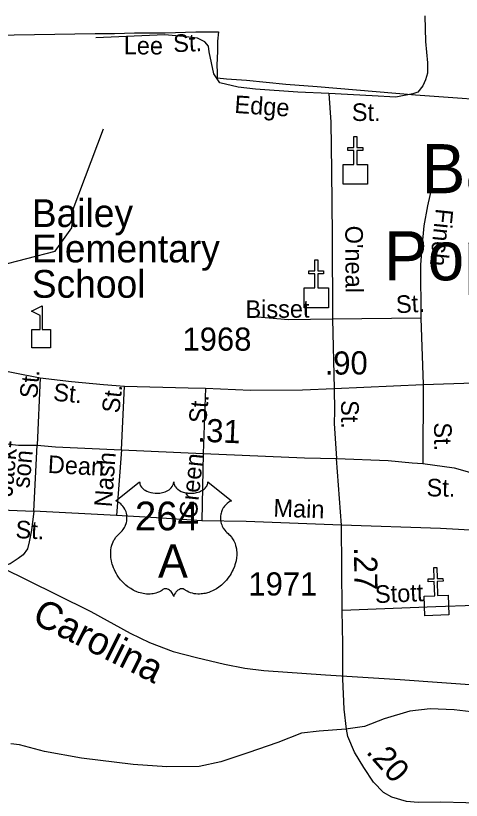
# Model space of a CAD drawing. Extents: x 2220236 to 2384410, y 720751 to 894131.
# Drawn here: x 2262372 to 2264776, y 738060 to 742297 of the extents above; entities that cross this region are included whole.
import ezdxf

# ---------------------------------------------------------------- set-up
doc = ezdxf.new("R2010")
doc.units = 0
for name, color, linetype in [('Exist Boundary Political City Limit New', 7, 'Continuous'), ('Exist Civil Demographics City Label', 7, 'Continuous'), ('Exist Cultural Church CELL', 7, 'Continuous'), ('Exist Cultural Educational Facility Elementary CELL', 7, 'Continuous'), ('Exist Cultural Educational Facility Elementary Label', 7, 'Continuous'), ('Exist Hydrographic Creek Single Shore', 7, 'Continuous'), ('Exist Railroad Mainline', 7, 'Continuous'), ('Exist Railroad Mainline Label', 7, 'Continuous'), ('Exist Road Non-System Type 51', 7, 'Continuous'), ('Exist Road Non-System Type 51 Label', 7, 'Continuous'), ('Exist Road Primary US Attributed', 7, 'Continuous'), ('Exist Road Primary US Label', 7, 'Continuous'), ('Exist Road Primary US Mileage Hundredths English Label', 7, 'Continuous'), ('Exist Road Primary US Shield CELL', 7, 'Continuous'), ('Exist Road Primary US Shield Number Label', 7, 'Continuous'), ('Exist Road Secondary Mileage Hundredths English Label', 7, 'Continuous'), ('Exist Road Secondary Type 51 Attributed', 7, 'Continuous'), ('Exist Road Secondary Type 51 Label', 7, 'Continuous'), ('Exist Road Secondary Type 51 Number Label', 7, 'Continuous'), ('Map Preparation Boundary City Limit Buffer Line', 7, 'Continuous')]:
    doc.layers.add(name, color=color, linetype=linetype)

msp = doc.modelspace()

# ---------------------------------------------------------------- linework, layer by layer
at = {"layer": 'Exist Boundary Political City Limit New'}
for points in [[(2261817.5, 742185.4), (2262801, 742201.3), (2262904.2, 742201.3), (2263013, 742203.9), (2263177.5, 742205.2), (2263344, 742209.2), (2263383, 742210.6), (2263466.8, 742210.6), (2263461.2, 742158.8), (2263460, 742105.8), (2263457.5, 742030.1), (2263458.8, 741992.9), (2263458.8, 741961.1), (2263508.8, 741955.8), (2263617.2, 741949.2), (2263829.5, 741927.9), (2263999.2, 741914.7), (2264529.8, 741869.6)], [(2264529.8, 741869.6), (2265081.2, 741829.8)], [(2264830.2, 738538.5), (2264738.2, 738548.2), (2264608.2, 738553.5), (2264498.2, 738540.9), (2264360.5, 738500.4), (2264253.8, 738458.8), (2264152.8, 738443.3), (2264008.8, 738432.6), (2263914.8, 738422.2), (2263787, 738371.4), (2263625.2, 738316.8), (2263479.5, 738268), (2263361.8, 738243.4), (2263187.8, 738240.6), (2263005.8, 738253.8), (2262727.5, 738288.2), (2262527.2, 738323.3), (2262393.2, 738358.8), (2262345.2, 738364.5)]]:
    msp.add_lwpolyline(points, dxfattribs=at)
at = {"layer": 'Exist Cultural Church CELL'}
for points in [[(2264139.3, 741493.1), (2264196.2, 741493.2), (2264196.2, 741569.4), (2264164.2, 741569.4), (2264164.2, 741585.3), (2264196.2, 741585.3), (2264196.2, 741645.5), (2264212.2, 741645.5), (2264212.2, 741585.3), (2264244.2, 741585.3), (2264244.2, 741569.4), (2264212.2, 741569.4), (2264212.2, 741493.2), (2264269.9, 741493.1), (2264269.9, 741386.7), (2264139.3, 741386.7)], [(2263928.5, 740826.6), (2263985.4, 740826.8), (2263985.4, 740902.9), (2263953.4, 740902.9), (2263953.4, 740918.9), (2263985.4, 740918.9), (2263985.4, 740979), (2264001.4, 740979), (2264001.4, 740918.9), (2264033.4, 740918.9), (2264033.4, 740902.9), (2264001.4, 740902.9), (2264001.4, 740826.8), (2264059.1, 740826.6), (2264059.1, 740720.2), (2263928.5, 740720.2)], [(2264575.6, 739162.9), (2264632.5, 739164.9), (2264629.9, 739241), (2264598, 739239.9), (2264597.4, 739255.9), (2264629.4, 739256.9), (2264627.4, 739317.1), (2264643.4, 739317.6), (2264645.4, 739257.5), (2264677.4, 739258.5), (2264677.9, 739242.6), (2264646, 739241.5), (2264648.5, 739165.4), (2264706.1, 739167.2), (2264709.6, 739060.8), (2264579.1, 739056.5)]]:
    msp.add_lwpolyline(points, close=True, dxfattribs=at)
at = {"layer": 'Exist Cultural Educational Facility Elementary CELL'}
msp.add_lwpolyline([(2262458.7, 740504.2), (2262458.7, 740602.1), (2262504.7, 740602.1), (2262504.7, 740677.2), (2262457.7, 740701.5), (2262514.3, 740730.7), (2262514.3, 740602.1), (2262560.4, 740602.1), (2262560.4, 740504.2)], close=True, dxfattribs=at)
at = {"layer": 'Exist Hydrographic Creek Single Shore'}
msp.add_lwpolyline([(2262277.2, 740946.5), (2262584.4, 741025.4), (2262675.4, 741151.5), (2262682.4, 741253), (2262845.4, 741685.9)], dxfattribs=at)
at = {"layer": 'Exist Railroad Mainline'}
msp.add_lwpolyline([(2262292.6, 739319), (2262591.9, 739171.9), (2262776.5, 739079.7), (2262989.6, 738961.8), (2263094, 738912.9), (2263222.3, 738864), (2263346.6, 738831.3), (2263498.8, 738794.8), (2263609, 738773.7), (2263711.1, 738760.6), (2264043.1, 738737.8), (2264447.2, 738711.7), (2264921.4, 738678.1), (2265321.4, 738655.9), (2265719.3, 738639.7), (2266099.3, 738615.3), (2266235.2, 738612.5), (2266365.4, 738597.6), (2266485.6, 738577), (2266585.7, 738545.9), (2266703.9, 738516.9), (2266814.4, 738474)], dxfattribs=at)
at = {"layer": 'Exist Road Non-System Type 51'}
for p, q in [((2264557, 740663.6), (2264081, 740658.7)), ((2264081, 740658.7), (2264090.7, 740284.5)), ((2264557, 740663.6), (2264570.6, 740305.4)), ((2262504, 740341.3), (2262487.9, 739977.3)), ((2262942.2, 739952.8), (2262959.8, 740296)), ((2263396.6, 740285.8), (2263383.4, 739933.5)), ((2264570.6, 740305.4), (2264569, 739878.1)), ((2262942.2, 739952.8), (2262915.6, 739598.7)), ((2263383.4, 739933.5), (2263376.1, 739569.5)), ((2262915.6, 739598.7), (2262470.4, 739622.1))]:
    msp.add_line(p, q, dxfattribs=at)
for points in [[(2264579.4, 742297.1), (2264582.7, 742157.1), (2264593.7, 742043.3), (2264594.4, 741987.3), (2264582.7, 741951.2), (2264569, 741919.1), (2264541.3, 741884.9), (2264515.5, 741874.6), (2264423.6, 741857.9), (2264295.6, 741864.5), (2264061.8, 741876.3)], [(2264061.8, 741876.3), (2263893.7, 741884.8), (2263665.7, 741900.7), (2263571.6, 741911.8), (2263473.5, 741934.8), (2263440.9, 741982.5), (2263415.9, 742102.2), (2263411.6, 742132.2), (2263391.5, 742156.1), (2263353.3, 742175.6), (2263275.1, 742184.8), (2263177.1, 742193.8), (2262803.5, 742178.3)], [(2264061.8, 741876.3), (2264071.4, 741722.1), (2264076.2, 741458.7), (2264080.2, 741110.1), (2264081, 740658.7)], [(2264619.6, 741381.6), (2264593.9, 741270.7), (2264574.6, 741161.5), (2264563.4, 741045.8), (2264555.4, 740951.1), (2264557, 740663.6)], [(2264081, 740658.7), (2263843.5, 740655.5), (2263634.8, 740673.2)], [(2264090.7, 740284.5), (2264092.3, 740162.4), (2264090.7, 740094.9), (2264102.7, 739905.4)], [(2262470.4, 739622.1), (2262456.7, 739518.6), (2262445.2, 739456.4), (2262435.6, 739418.5), (2262411.9, 739386.1), (2262386.1, 739365.9), (2262342.4, 739337.6), (2262218.9, 739294.4), (2262131, 739277.6), (2262057, 739276.9), (2261967, 739283.9), (2261789, 739292.4), (2261482.9, 739319.5), (2261057, 739347.5)], [(2263376.1, 739569.5), (2263132.2, 739585.6), (2262915.6, 739598.7)], [(2264129.5, 739546.1), (2263615.6, 739565.3), (2263376.1, 739569.5)], [(2265471.4, 739484.9), (2265293.5, 739497.2), (2265113.5, 739503.5), (2264663.5, 739527.4), (2264129.5, 739546.1)], [(2265997.1, 739150), (2265901.8, 739147.8), (2265404.8, 739134.4), (2265059, 739119.1), (2264639.4, 739105.2), (2264133.8, 739084.6)]]:
    msp.add_lwpolyline(points, dxfattribs=at)
at = {"layer": 'Exist Road Primary US Attributed'}
for points in [[(2261239.8, 740172.1), (2261385.9, 740142.9), (2261438.2, 740132.2), (2261767.2, 740058.1), (2261937.2, 740022.7), (2262035.1, 740003.7), (2262116.3, 739993), (2262185.5, 739990.5), (2262249.8, 739989), (2262321.4, 739984.7), (2262386.3, 739977.7), (2262487.9, 739977.3)], [(2262487.9, 739977.3), (2262586.3, 739969.6), (2262942.2, 739952.8), (2263383.4, 739933.5), (2263929.3, 739910.2), (2264102.7, 739905.4)], [(2264102.7, 739905.4), (2264382, 739894.2), (2264510.4, 739882.9), (2264569, 739878.1), (2264738.4, 739855.6), (2264820.6, 739832.6), (2264898.9, 739804.2), (2264977.6, 739770.5), (2265061, 739720.7), (2265178.2, 739661.3), (2265314.4, 739591.3), (2265471.4, 739484.9), (2265558.1, 739421.8), (2265688.8, 739340.9), (2265827.4, 739258.3), (2265906.6, 739208.1), (2265997.1, 739150), (2266082.8, 739094.9), (2266256.1, 738983.4), (2266450.4, 738858.1), (2266604.5, 738761.8), (2266771.4, 738650.9), (2267068.3, 738464.4), (2267306.7, 738310.4)]]:
    msp.add_lwpolyline(points, dxfattribs=at)
at = {"layer": 'Exist Road Primary US Shield CELL'}
msp.add_lwpolyline([(2263040.5, 739779.4), (2263040.8, 739774.1), (2263042.1, 739767.8), (2263043.1, 739764.5), (2263046, 739758.3), (2263050.9, 739750.9), (2263057.7, 739743.7), (2263065.4, 739737.4), (2263070.5, 739734.1), (2263079.3, 739729.4), (2263089.3, 739725.2), (2263100.3, 739722), (2263111.7, 739719.7), (2263124, 739718.3), (2263136.3, 739718.1), (2263149.5, 739719.1), (2263164.1, 739721.9), (2263170.8, 739723.7), (2263178.3, 739726.2), (2263185.3, 739729.1), (2263193, 739733.2), (2263199.2, 739737.2), (2263204, 739740.7), (2263210.8, 739747.2), (2263216.2, 739754), (2263218.5, 739757.8), (2263220.5, 739761.4), (2263223.2, 739769.2), (2263224, 739772.6), (2263224.5, 739779.7), (2263224.9, 739773.7), (2263225.6, 739770), (2263226.5, 739766.4), (2263228.1, 739762.5), (2263230.8, 739757), (2263233.8, 739752.4), (2263239.6, 739745.7), (2263243.1, 739742.3), (2263246.4, 739739.7), (2263255.1, 739733.7), (2263265.3, 739728.5), (2263270.4, 739726.3), (2263275.5, 739724.5), (2263282.1, 739722.5), (2263288.8, 739720.9), (2263295.5, 739719.8), (2263302.3, 739718.8), (2263309.3, 739718.3), (2263315, 739718.1), (2263322, 739718.2), (2263328.5, 739718.6), (2263335.1, 739719.3), (2263342.4, 739720.5), (2263348.2, 739721.8), (2263356, 739723.9), (2263362.9, 739726.4), (2263369.1, 739729), (2263377.1, 739733.2), (2263383.5, 739737.3), (2263388.2, 739741.1), (2263393.9, 739746.2), (2263399.2, 739752.4), (2263402.3, 739756.9), (2263404.5, 739761.5), (2263406.5, 739766.4), (2263407.8, 739771.5), (2263408.4, 739776), (2263408.5, 739779.8), (2263537.1, 739677.4), (2263534.1, 739676.2), (2263527.1, 739672.8), (2263521.6, 739669.5), (2263512.7, 739663.3), (2263508.9, 739659.9), (2263505.1, 739656.3), (2263501.6, 739652.5), (2263498.5, 739649), (2263494.8, 739643.8), (2263491.5, 739638.6), (2263488.2, 739632.9), (2263485.8, 739628), (2263481.9, 739617.6), (2263480, 739611.1), (2263478.8, 739605.6), (2263477.2, 739594.1), (2263476.9, 739588.6), (2263476.9, 739583.2), (2263477.2, 739577.5), (2263477.7, 739572.1), (2263478.7, 739566.4), (2263479.6, 739561.3), (2263481.2, 739555.2), (2263483.5, 739548), (2263486.3, 739541.1), (2263492.2, 739530), (2263499.7, 739518.6), (2263505.1, 739512.2), (2263510.4, 739506.7), (2263518.4, 739500), (2263522.7, 739496.2), (2263527.6, 739491.3), (2263535.6, 739481.9), (2263538.9, 739477.5), (2263542.2, 739472.6), (2263545.3, 739467.5), (2263548.3, 739462), (2263550.7, 739457.2), (2263555.2, 739446.2), (2263558.5, 739435.5), (2263560.1, 739429.9), (2263562.5, 739417.3), (2263563.4, 739411), (2263564.4, 739398.7), (2263564.4, 739383.8), (2263563.2, 739369.7), (2263560.6, 739353.2), (2263558.4, 739343.3), (2263555, 739331.9), (2263551.7, 739321.9), (2263545.9, 739307.2), (2263540.7, 739296.6), (2263533.9, 739284.1), (2263529.3, 739276.6), (2263523.9, 739268.6), (2263517.1, 739259.3), (2263509.2, 739249.4), (2263499.7, 739239), (2263492, 739231.3), (2263482, 739222.4), (2263475.9, 739217.3), (2263467.3, 739210.8), (2263455.4, 739202.9), (2263443.7, 739196.1), (2263433.8, 739191.1), (2263425, 739187.3), (2263413.6, 739182.9), (2263394.6, 739177.7), (2263387.7, 739176.2), (2263379.5, 739175), (2263371.8, 739174.3), (2263364.4, 739173.8), (2263354.4, 739173.8), (2263344.4, 739174.6), (2263335, 739175.9), (2263325.2, 739178), (2263314.9, 739181), (2263305.6, 739184.7), (2263296.2, 739189.3), (2263280.3, 739199.3), (2263275.7, 739201.8), (2263273.1, 739202.5), (2263267, 739202.8), (2263261.2, 739201.5), (2263255.3, 739199.2), (2263251.7, 739197.3), (2263247, 739194.2), (2263243.3, 739191.3), (2263238.9, 739187.1), (2263235.9, 739183.6), (2263233.6, 739180.9), (2263229.1, 739173.8), (2263227.5, 739170.5), (2263225.8, 739166.1), (2263224.4, 739159.8), (2263222.3, 739167.8), (2263220, 739173.1), (2263217.2, 739177.7), (2263214.4, 739181.7), (2263209.9, 739186.9), (2263205.9, 739190.8), (2263201, 739194.7), (2263195.9, 739197.8), (2263191.7, 739199.9), (2263187.9, 739201.4), (2263183.3, 739202.5), (2263179.5, 739202.8), (2263176.4, 739202.8), (2263172.1, 739201.8), (2263166.3, 739197.6), (2263160.8, 739193.8), (2263154.8, 739190.1), (2263147.6, 739186.3), (2263142.4, 739183.8), (2263136.2, 739181.4), (2263128.9, 739179), (2263121, 739176.9), (2263112.8, 739175.3), (2263105.7, 739174.2), (2263098, 739173.5), (2263091.1, 739173.3), (2263083.9, 739173.4), (2263077.2, 739173.9), (2263069.3, 739174.6), (2263059.6, 739176), (2263051.6, 739177.8), (2263043.1, 739180.1), (2263034.3, 739182.8), (2263025, 739186.4), (2263013.3, 739191.5), (2263005.2, 739195.7), (2262992.3, 739203.1), (2262977.3, 739213.5), (2262965.9, 739222.7), (2262957.6, 739230.2), (2262945.4, 739242.7), (2262938.2, 739250.8), (2262926.9, 739265.4), (2262919.7, 739275.9), (2262915, 739283.7), (2262908.2, 739296.1), (2262904.4, 739304), (2262899.6, 739315.4), (2262895.8, 739325.8), (2262892.6, 739335.7), (2262890.9, 739342), (2262888.4, 739353), (2262886.9, 739360.8), (2262885.5, 739371.5), (2262884.7, 739382.8), (2262884.6, 739393.3), (2262884.8, 739401.9), (2262885.8, 739412), (2262887.5, 739422.7), (2262889.6, 739431.9), (2262891.4, 739438.5), (2262894.2, 739446.6), (2262897.8, 739455.5), (2262902, 739464), (2262906.1, 739471.1), (2262911.2, 739478.7), (2262916.2, 739485.1), (2262922.8, 739492.3), (2262929.6, 739498.8), (2262935.9, 739503.9), (2262943.3, 739511.2), (2262947.2, 739515.6), (2262951.8, 739521.7), (2262955.6, 739527.4), (2262958.5, 739532.5), (2262962.4, 739540.1), (2262964.8, 739545.7), (2262967.8, 739554.3), (2262969.2, 739560.4), (2262970.8, 739568.3), (2262971.7, 739575.6), (2262972.1, 739584.8), (2262971.9, 739592.4), (2262970.9, 739601.3), (2262969.2, 739609.8), (2262967.2, 739617.3), (2262964, 739625.8), (2262961.1, 739632), (2262956.2, 739640.4), (2262950.7, 739648.3), (2262945, 739654.7), (2262939.3, 739660.4), (2262933.9, 739664.6), (2262928.7, 739668.3), (2262922.1, 739672.3), (2262915.8, 739675.4), (2262911.9, 739677)], close=True, dxfattribs=at)
at = {"layer": 'Exist Road Secondary Type 51 Attributed'}
for points in [[(2261387.4, 740581.4), (2261642.8, 740527), (2261872.2, 740470), (2262072.3, 740427.6), (2262358.6, 740370.6), (2262504, 740341.3), (2262672.9, 740322.1), (2262844.9, 740305.7), (2262959.8, 740296), (2263301.6, 740287.2), (2263396.6, 740285.8), (2263639.1, 740275.5), (2263918.9, 740276.5), (2264090.7, 740284.5), (2264570.6, 740305.4), (2265395.7, 740332.7), (2265870.1, 740351.9), (2266084.5, 740362.5), (2266279.4, 740366.4), (2266759.4, 740372.8), (2267114.1, 740384.1), (2267238.5, 740385.7), (2267291.5, 740385.7)], [(2261072.2, 739690.5), (2261352.5, 739676.2), (2261654.1, 739660.5), (2262021.9, 739639.7), (2262470.4, 739622.1), (2262487.9, 739977.3)], [(2264136.5, 738731.8), (2264137.6, 738904.2), (2264133.8, 739084.6), (2264129.5, 739546.1), (2264102.7, 739905.4)], [(2265133.3, 738040.6), (2264800.2, 738047), (2264665.3, 738050.2), (2264543.3, 738048.6), (2264480.7, 738053.4), (2264400.5, 738077.5), (2264357.1, 738101.6), (2264302.6, 738157.8), (2264249.6, 738236.5), (2264199.8, 738320), (2264164.5, 738405.2), (2264157.2, 738443.7), (2264143.6, 738551.3), (2264136.4, 738715.2), (2264136.5, 738731.8)]]:
    msp.add_lwpolyline(points, dxfattribs=at)
at = {"layer": 'Map Preparation Boundary City Limit Buffer Line'}
for points in [[(2261817.5, 742185.4), (2262801, 742201.3), (2262904.2, 742201.3), (2263013, 742203.9), (2263177.5, 742205.2), (2263344, 742209.2), (2263383, 742210.6), (2263466.8, 742210.6), (2263461.2, 742158.8), (2263460, 742105.8), (2263457.5, 742030.1), (2263458.8, 741992.9), (2263458.8, 741961.1), (2263508.8, 741955.8), (2263617.2, 741949.2), (2263829.5, 741927.9), (2263999.2, 741914.7), (2264529.8, 741869.6)], [(2264529.8, 741869.6), (2265081.2, 741829.8)], [(2264830.2, 738538.5), (2264738.2, 738548.2), (2264608.2, 738553.5), (2264498.2, 738540.9), (2264360.5, 738500.4), (2264253.8, 738458.8), (2264152.8, 738443.3), (2264008.8, 738432.6), (2263914.8, 738422.2), (2263787, 738371.4), (2263625.2, 738316.8), (2263479.5, 738268), (2263361.8, 738243.4), (2263187.8, 738240.6), (2263005.8, 738253.8), (2262727.5, 738288.2), (2262527.2, 738323.3), (2262393.2, 738358.8), (2262345.2, 738364.5)]]:
    msp.add_lwpolyline(points, dxfattribs=at)

# ---------------------------------------------------------------- texts
at = {"layer": 'Exist Civil Demographics City Label'}
for s, p in [('Bailey', (2264561.8, 741338.5)), ('Pop. 681', (2264358.4, 740868.1))]:
    msp.add_text(s, height=265, dxfattribs=at).set_placement(p)
at = {"layer": 'Exist Cultural Educational Facility Elementary Label'}
for s, p in [('Bailey', (2262458.8, 741155.9)), ('Elementary', (2262458.8, 740964.8)), ('School', (2262458.8, 740773.8))]:
    msp.add_text(s, height=150, dxfattribs=at).set_placement(p)
at = {"layer": 'Exist Railroad Mainline Label'}
msp.add_text('Carolina', height=150, rotation=333.4602, dxfattribs=at).set_placement((2262452.7, 739022.3))
at = {"layer": 'Exist Road Non-System Type 51 Label'}
for s, rotation, p in [('Lee', 359.7971, (2262954.7, 742088.4)), ('Lee', 359.7971, (2262954.7, 742088.4)), ('St.', 2.3755, (2263223.5, 742099.8)), ('Edge', 356.0103, (2263550.2, 741772.4)), ('St.', 359.8804, (2264185.3, 741728.7)), ('Finch', 264.0209, (2264639, 741258.6)), ("O'neal", 270.2481, (2264150.1, 741163)), ('St.', 3.1498, (2264426, 740689.8)), ('Bisset', 0.3486, (2263611.7, 740664.6)), ('St.', 85.049, (2262487.7, 740227.2)), ('St.', 83.6617, (2262930.8, 740147.5)), ('St.', 84.8113, (2263399.8, 740092.5)), ('St.', 270.2481, (2264127.7, 740221.1)), ('St.', 270.5674, (2264628.9, 740100.6)), ('Jack-', 84.8412, (2262354, 739697.9)), ('son', 84.8412, (2262445.6, 739742.9)), ('Nash', 85.7039, (2262890, 739641.1)), ('Green', 84.0033, (2263347.9, 739577.4)), ('Main', 357.86, (2263761.1, 739592.7)), ('Stott', 2.3332, (2264312.2, 739124.7))]:
    msp.add_text(s, height=95, rotation=rotation, dxfattribs=at).set_placement(p)
at = {"layer": 'Exist Road Primary US Label'}
for s, rotation, p in [('Dean', 356.958, (2262543.5, 739828.3)), ('St.', 358.8872, (2264588.1, 739701.8))]:
    msp.add_text(s, height=95, rotation=rotation, dxfattribs=at).set_placement(p)
at = {"layer": 'Exist Road Primary US Mileage Hundredths English Label'}
msp.add_text('.31', height=125, rotation=357.5601, dxfattribs=at).set_placement((2263351.3, 739997.4))
at = {"layer": 'Exist Road Primary US Shield Number Label'}
for s, height, p in [('264', 155, (2263014.9, 739518.1)), ('A', 180, (2263140, 739263.2))]:
    msp.add_text(s, height=height, dxfattribs=at).set_placement(p)
at = {"layer": 'Exist Road Secondary Mileage Hundredths English Label'}
for s, rotation, p in [('.90', 0.5212, (2264039.5, 740358.2)), ('.27', 270.534, (2264197.2, 739426.6)), ('.20', 311.6503, (2264258.5, 738318.8))]:
    msp.add_text(s, height=125, rotation=rotation, dxfattribs=at).set_placement(p)
at = {"layer": 'Exist Road Secondary Type 51 Label'}
for rotation, p in [(354.5541, (2262571.6, 740218.5)), (357.3619, (2262369.3, 739476.2))]:
    msp.add_text('St.', height=95, rotation=rotation, dxfattribs=at).set_placement(p)
at = {"layer": 'Exist Road Secondary Type 51 Number Label'}
for s, p in [('1968', (2263271.8, 740488.1)), ('1971', (2263627.5, 739166))]:
    msp.add_text(s, height=125, dxfattribs=at).set_placement(p)

doc.saveas('drawing.dxf')
